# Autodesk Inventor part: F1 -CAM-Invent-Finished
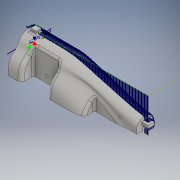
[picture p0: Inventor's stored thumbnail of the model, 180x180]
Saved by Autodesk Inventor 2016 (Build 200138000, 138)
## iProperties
Created: 2016-01
Part Number: F1 -CAM-Invent-Finished
Material: Generic
Document SubType Name: Modeling
Designer: PhillipD
Density: 1 g/cm^3
Appearance: Default
Author: PhillipD
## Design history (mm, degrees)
sketch "Sketch1"
  geometry: L1 (0, 0)-(65, 0); L2 (65, 0)-(65, -210); L3 (65, -210)-(0, -210); L4 (0, -210)-(0, 0)
  constraints: 8 end point, 2 parallel, 1 horizontal, 1 perpendicular
  dimensions: "d0" = 65 distance of L2.end L3.end; "d1" = 210 distance of L1.end L2.end
extrude "Extrusion1" new body sketch "Sketch1" distance "d2" = 50; taper "d3" = 0 deg
sketch "Sketch3"
  geometry: L1 (65, 0)-(0, 0) reference; L2 (65, 0)-(65, 50) reference; C1 r 9.5 at (32.5, 29)
  constraints: 1 centre point
  dimensions: "d4" = 19 diameter of C1; "d5" = 29 distance from line of L1 C1.centre; "d6" = 32.5 distance from line of L2 C1.centre
extrude "Extrusion2" cut sketch "Sketch3" distance "d7" = 52; taper "d8" = 0 deg
sketch "Sketch4"
  geometry: L1 (29.5, 6)-(35.5, 6); L2 (35.5, 6)-(35.5, 0); L3 (35.5, 0)-(29.5, 0); L4 (29.5, 0)-(29.5, 6); L5 (65, 0)-(0, 0) reference; 2 further points
  constraints: 8 end point, 2 midpoint, 2 parallel, 1 collinear, 1 horizontal, 1 perpendicular, 1 vertical alignment
  dimensions: "d9" = 6 distance of L2.end L3.end; "d10" = 6 distance of L1.end L2.end
extrude "Extrusion3" cut sketch "Sketch4" stored distance "d11" = 52; taper "d12" = 0 deg
sketch "Sketch5"
  geometry: L1 (210, 0)-(0, 0) reference; L2 (0, 0)-(0, 50) reference; L3 (210, 0)-(210, 50) reference; 2 further points
  dimensions: "d13" = 10 distance from line of L1 point (40, 10); "d14" = 40 distance from line of point (40, 10) L2; "d15" = 10 distance from line of L1 point (150, 10); "d16" = 60 distance from line of point (150, 10) L3
hole "Hole1" sketch "Sketch5" at (40, 10), (150, 10) diameter "d17" = 4; stored, may be unused: countersink angle "d21" = 90 deg, drill point angle "d23" = 118 deg; dims "d18" = 6, "d19" = 4, "d20" = 2, "d22" = 8
sketch "Sketch6"
  geometry: L1 (0, 190)-(-19, 190); L2 (-19, 190)-(-19, 150); L3 (-19, 150)-(0, 150); L4 (0, 150)-(0, 190); L5 (0, 0)-(-19, 0); L6 (-19, 0)-(-19, 98); L7 (-19, 98)-(0, 98); L8 (0, 98)-(0, 0); L9 (0, 210)-(-65, 210) reference
  constraints: 16 end point, 4 parallel, 2 horizontal, 2 perpendicular
  dimensions: "d24" = 19 distance of L3.end L2.end; "d25" = 40 distance of L2.end L1.end; "d26" = 19 distance of L6.end L7.end; "d27" = 98 distance of L5.end L6.end; "d28" = 20 distance between parallel lines of L9 L1
extrude "Extrusion4" cut sketch "Sketch6" stored distance "d29" = 10; taper "d30" = 0 deg
workplane "Work Plane1"
mirror "Mirror1"
sketch "Sketch7"
  geometry: L1 (0, 210)-(-65, 210) reference; 3 further points
  constraints: 1 midpoint, 1 vertical alignment
  dimensions: "d31" = 105 distance from line of point (-32.5, 105) L1
feature "Form1"
split "Split1"
sketch "Sketch8"
  geometry: L1 (20, 0)-(0, 0) reference; 3 further points
  constraints: 1 midpoint, 1 vertical alignment
  dimensions: "d32" = 51 distance from line of L1 point (10, 51)
feature "Form2"
feature "Form3"
workplane "Work Plane2"
sketch "Sketch9"
  geometry: L1 (-4, 6)-(4, 6); L2 (4, 6)-(4, 14); L3 (4, 14)-(-4, 14); L4 (-4, 14)-(-4, 6); L5 (-3, 0)-(3, 0) reference; L6 (32.5, 20)-(32.5, 0) reference; 5 further points
  constraints: 8 end point, 4 midpoint, 2 parallel, 1 horizontal, 1 horizontal alignment, 1 perpendicular, 1 vertical alignment
  dimensions: "d33" = 8 distance of L3.end L2.end; "d34" = 8 distance of L2.end L1.end
extrude "Extrusion5" new body sketch "Sketch9" distance "d35" = 5; taper "d37" = 0 deg; dims "d36" = 3, "d38" = 0
combine "Combine5"
combine "Combine6"
  body "Solid4"
workplane "Work Plane7"
split "Split2"
  body "Solid1"
sketch "Sketch11"
  geometry: L1 (-2, 7)-(8, 7); L2 (8, 7)-(8, 3); L3 (8, 3)-(-2, 3); L4 (-2, 3)-(-2, 7); L5 (14.966, -6)-(6, -6) reference; L6 (6, 0)-(0, 0) reference; 3 further points
  constraints: 8 end point, 2 midpoint, 2 parallel, 1 horizontal, 1 perpendicular, 1 vertical alignment
  dimensions: "d47" = 10 distance of L2.end L3.end; "d48" = 4 distance of L1.end L2.end; "d49" = 13 distance between parallel lines of L5 L1
extrude "Extrusion7" join sketch "Sketch11" distance "d50" = 10; taper "d51" = 0 deg
combine "Combine7"
fillet "Fillet1" dims "d52" = 3
fillet "Fillet2" dims "d53" = 5
fillet "Fillet3" dims "d54" = 8
fillet "Fillet4" dims "d55" = 3
sketch "Sketch17"
  geometry: L1 (3, 23)-(3, -6); L2 (3, 23)-(-29.5, 23); L3 (3, 23)-(37, 23); C1 r 9.5 at (3, 23) reference; 1 further point
  constraints: 6 end point, 1 horizontal, 1 point on line, 1 vertical
  dimensions: "d56" = 32.5 distance of L1.start L2.end
body "Srf1"
body "Solid2"
body "Solid3"
body "Solid6"
body "Solid7"
other parameters: "d46" = -35
